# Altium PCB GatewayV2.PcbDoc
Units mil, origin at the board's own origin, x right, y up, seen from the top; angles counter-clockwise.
Board outline 1970 x 2515 mil, 2 copper layers (Top Layer, Bottom Layer); 53 components, 43 nets, 217 pads, 138 vias.
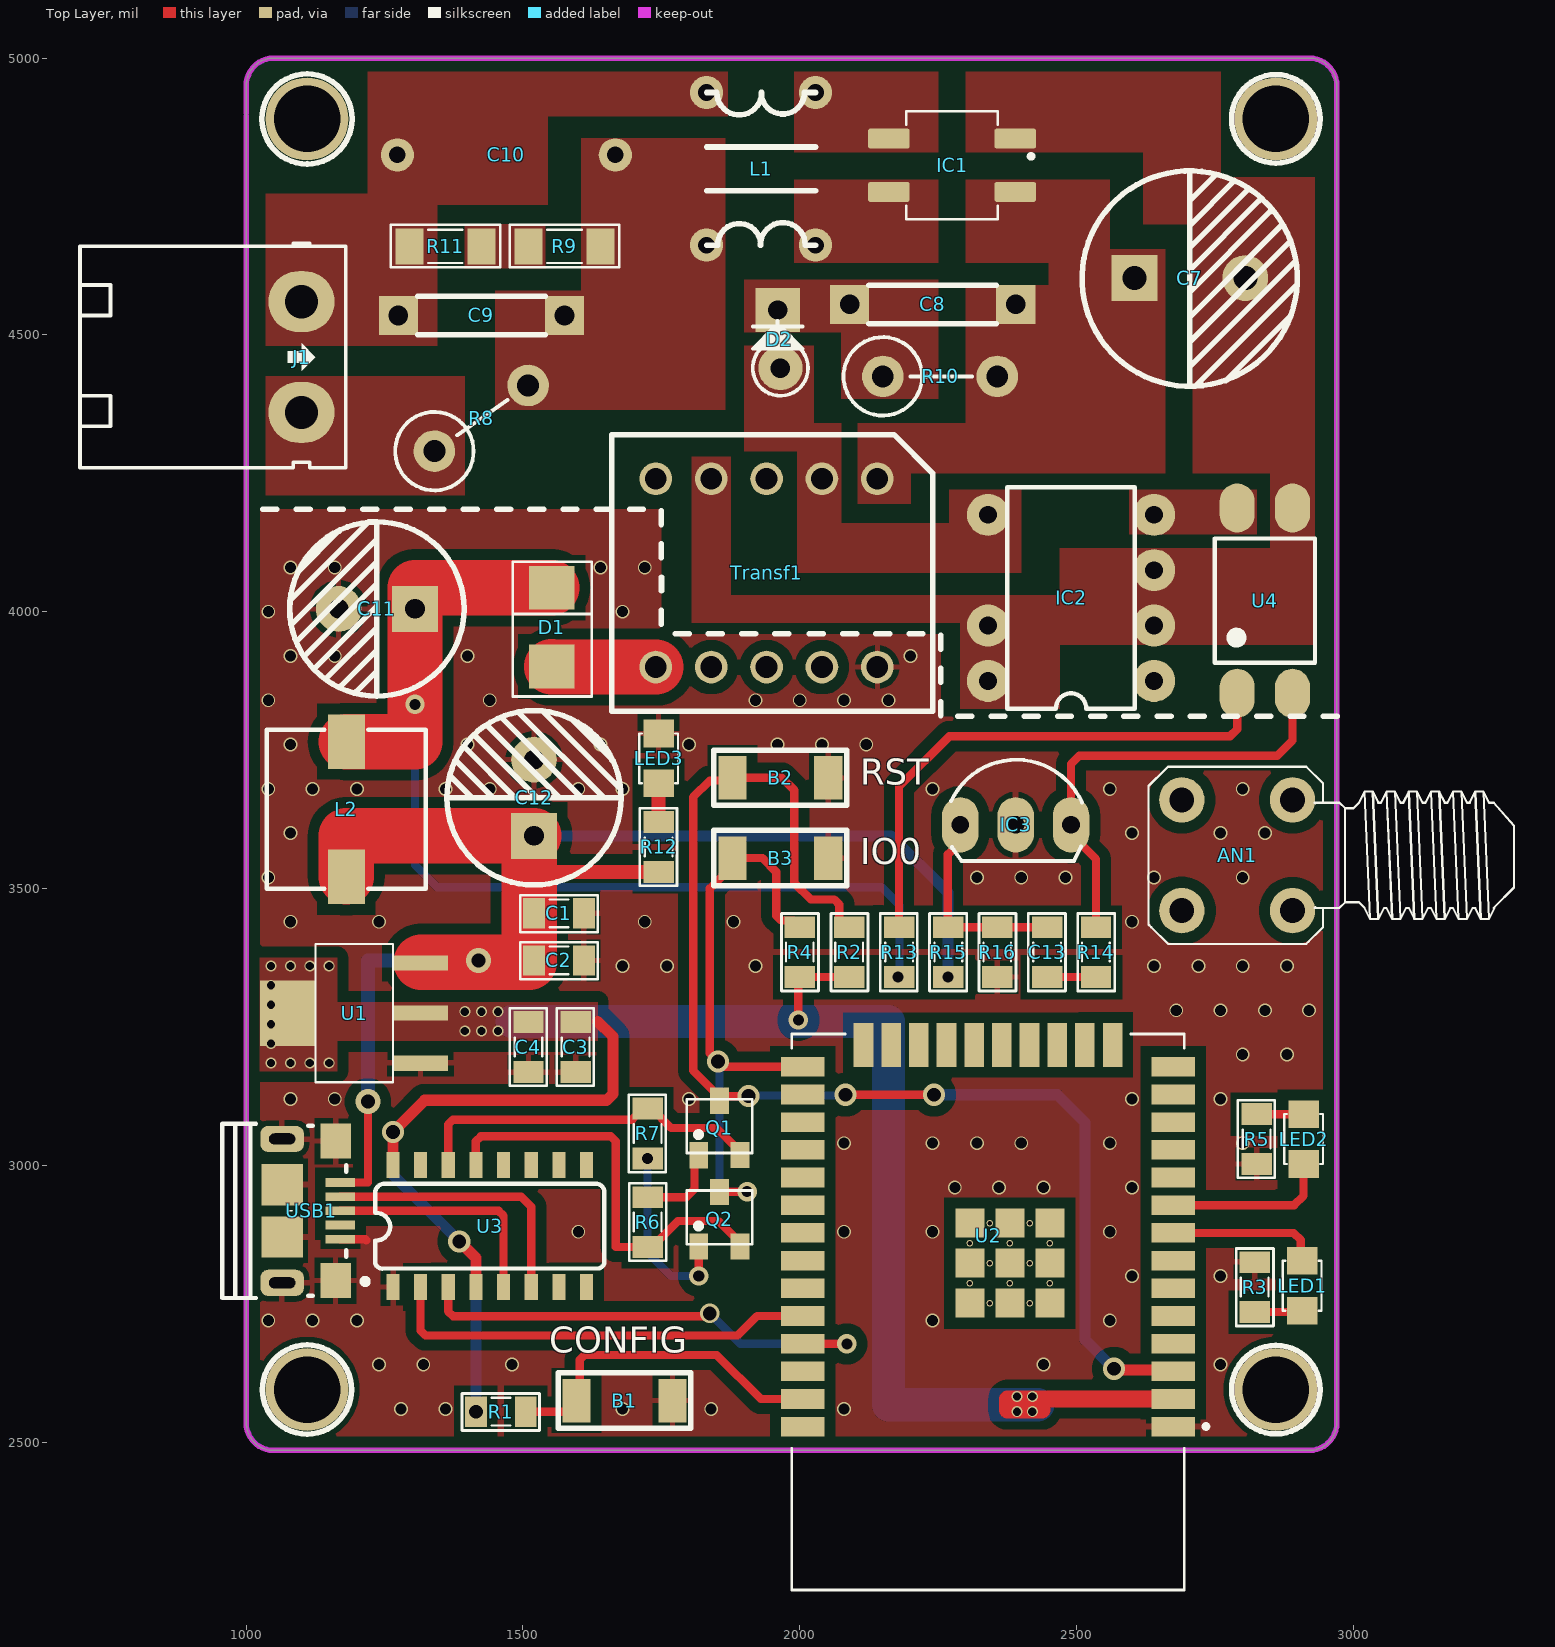
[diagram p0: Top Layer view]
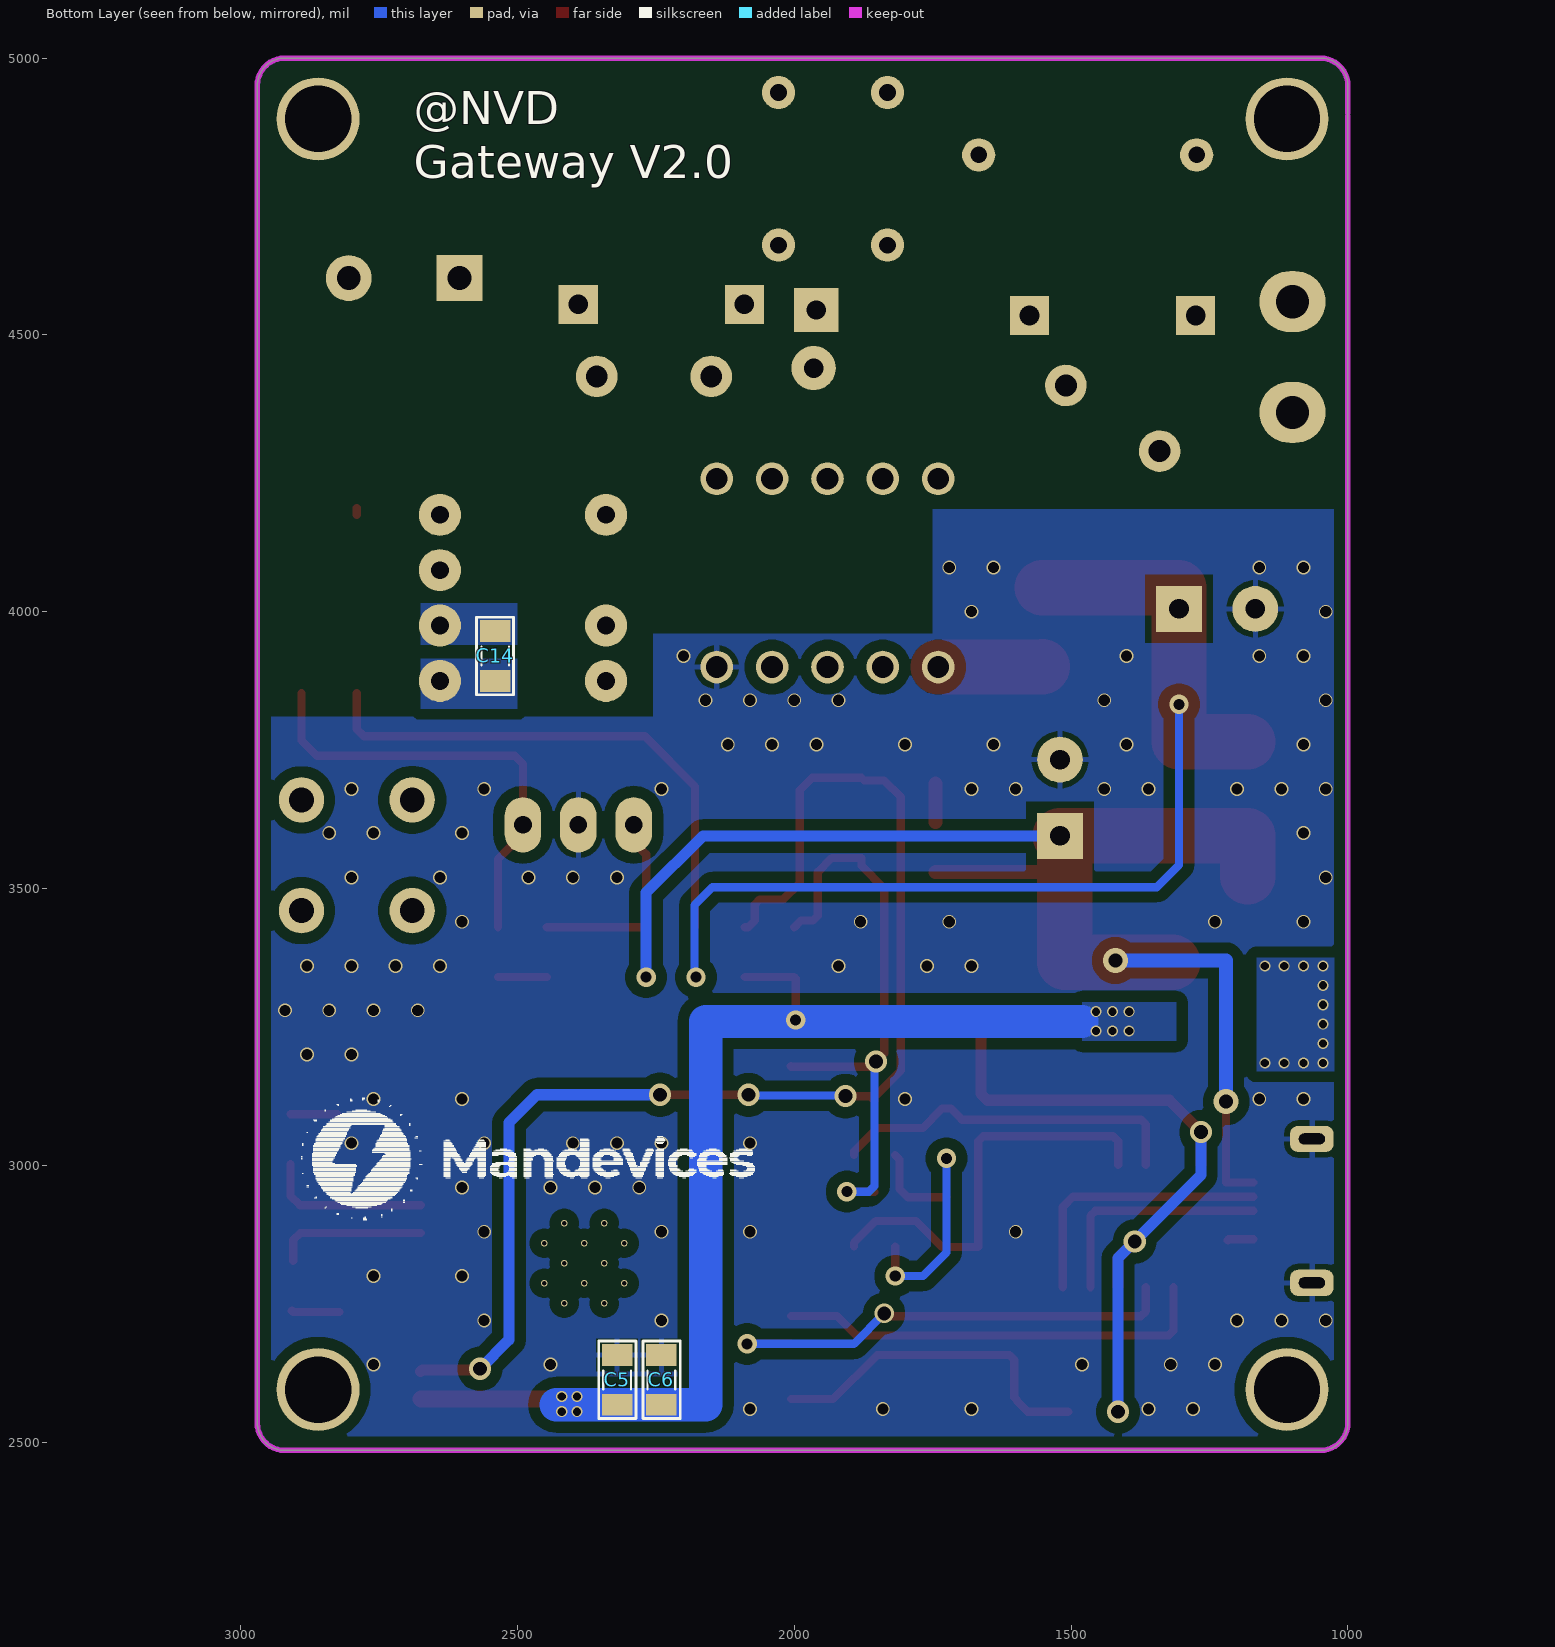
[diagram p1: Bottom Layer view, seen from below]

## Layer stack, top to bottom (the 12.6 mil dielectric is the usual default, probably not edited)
Top Solder: solder mask 0.4, Solder Resist, Dk 3.5
Top Layer: signal copper 1.4
Dielectric 1: dielectric 12.6, FR-4, Dk 4.8
Bottom Layer: signal copper 1.4
Bottom Solder: solder mask 0.4, Solder Resist, Dk 3.5

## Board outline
1050.01,2485 cw(c1050.01,2535) 1000.01,2535 1000.01,2570 1000.47,4895 1000,4900 1000,4950 cw(c1050,4950) 1050,5000 2920,5000 cw(c2920,4950) 2970,4950 2970,2535 cw(c2920,2535) 2920,2485

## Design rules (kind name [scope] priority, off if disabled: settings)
Clearance GND_Clearance [InNet('GND')] p1: gap=15 ignorepadtopadclearanceinfootprint=TRUE
Clearance [All] p2: gap=15 ignorepadtopadclearanceinfootprint=TRUE
PolygonConnect [All] p1: thpad.connectstyle=Relief thpad.reliefconductorwidth=10 thpad.reliefentries=4 thpad.polygonreliefangle="90 Angle" thpad.airgapwidth=10 smdpad.connectstyle=Relief smdpad.reliefconductorwidth=10 smdpad.reliefentries=4 smdpad.polygonreliefangle="90 Angle" smdpad.airgapwidth=10 via.connectstyle=Direct via.reliefconductorwidth=10 via.reliefentries=4 via.polygonreliefangle="90 Angle" via.airgapwidth=10
RoutingVias [All] p1: holewidth=28 width=50 viastyle="Through Hole" minholewidth=10 minwidth=10 maxholewidth=100 maxwidth=100
SolderMaskExpansion [All] p1: expansion=4 istentingtop=FALSE
Width [All] p1: maxlimit=100 minlimit=10 preferedwidth=50
30 further rules are at their usual default settings.

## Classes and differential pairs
component class Power: C7 C8 C9 C10 C11 C12 C13 C14 D1 D2 IC1 IC2 IC3 J1 L1 L2 LED3 R8 R9 R10 R11 R12 R13 R14 R15 R16 Transf1 U4
component class ESP32: AN1 B1 B2 B3 C1 C2 C3 C4 C5 C6 LED1 LED2 Q1 Q2 R1 R2 R3 R4 R5 R6 R7 U1 U2 U3 USB1

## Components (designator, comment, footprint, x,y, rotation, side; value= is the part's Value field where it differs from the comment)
AN1 "ANTENA" "DE ANTEN SMA CONG" 2790,3560 r90 top
B1 "Button 3x4x2.5" "Button 3x4x2.5" 1683.39,2575 r180 top
B2 "Button 3x4x2.5" "Button 3x4x2.5" 1965,3700 r180 top
B3 "Button 3x4x2.5" "Button 3x4x2.5" 1965,3555 r180 top
C1 "10uF" CAP_0805 1562.85,3543.11 r0 top value=33p
C2 "100nF" CAP_0805 1562.85,3458.11 r0 top value=33p
C3 "10uF" CAP_0805 1683.11,3215.86 r270 top value=33p
C4 "100nF" CAP_0805 1598.11,3215.86 r270 top value=33p
C5 "100nF" CAP_0805 2408.11,2610.35 r90 bottom value=33p
C6 "10uF" CAP_0805 2328.11,2610.35 r90 bottom value=33p
C7 "10uF/400V" C10mm 2705,4605 r0 top
C8 "1nF/400V" 103/2KV 2390,4555 r180 top
C9 "14D471K" 103/2KV 1275,4535 r0 top
C10 "0.1uF/275v" "Cap AC filter" 1470,4825 r0 top
C11 "680uF/16V" C8mm 1242.75,4002.3 r180 top
C12 "470uF/16V" C8mm 1517.3,3657.25 r90 top
C13 "100nF" CAP_0805 2534.94,3387.15 r270 top value=33p
C14 "100nF" CAP_0805 2451.89,3922.15 r270 bottom value=33p
D1 "SS14" DO-214AC(SMA) 1555,3950 r270 top value=1N5007
D2 "1N4937" DIO-1AN 1960,4495 r270 top value=1N5007
IC1 "MB6S" MB6S 2280,4795 r180 top
IC2 "TNY264" TNY264 2686.85,3808.46 r90 top
IC3 "TL431" qto-92 2390,3615 r0 top
J1 "KF2" KF2-5.08T 1100,4560 r270 top
L1 "Inductor EE8.3" "Inductor EE8.3" 1930,4800 r90 top
L2 "22uH" L_SMD 1175,3655 r0 top value="150 mH"
LED1 "LED" LED-0805-Red 2907.5,2827.5 r270 top value="LED 3 ly Single Colour"
LED2 "LED" LED-0805-Red 2910,3002.5 r90 top value="LED 3 ly Single Colour"
LED3 "LED" LED-0805-Red 1745,3690 r90 top value="LED 3 ly Single Colour"
Q1 "C1815" SOT23D 1855,3067.5 r0 top
Q2 "C1815" SOT23D 1855,2902.5 r0 top
R1 "10k" RES-SMD-0805 1460,2555 r0 top
R2 "10k" RES-SMD-0805 2089.17,3385 r90 top
R3 "1k" RES-SMD-0805 2821.5,2780 r90 top
R4 "10k" RES-SMD-0805 2000,3385 r90 top
R5 "1k" RES-SMD-0805 2825,3047.5 r270 top
R6 "10k" RES-SMD-0805 1725,2897.5 r90 top
R7 "10k" RES-SMD-0805 1725,3057.5 r270 top
R8 "2R/2W" RES-1WW 1393.24,4327.28 r35 top
R9 "1M" RES-SMD-1206 1575,4660 r0 top
R10 "200k/2W" RES-1WW 2215,4425 r0 top
R11 "1M" RES-SMD-1206 1360,4660 r0 top
R12 "1k" RES-SMD-0805 1745,3575 r270 top
R13 "200R" RES-SMD-0805 2179.33,3385 r270 top
R14 "3.3k" RES-SMD-0805 2535,3385 r90 top
R15 "11k" RES-SMD-0805 2268.5,3385 r270 top
R16 "10k" RES-SMD-0805 2356.67,3385 r90 top
Transf1 "Transformer EE12.7" "Transformer EE12.7" 1940,4070 r180 top
U1 "LM1117-ADJ" LM1117-SOP 1265,3275 r90 top
U2 "ESP32-WROOM-32" MODULE_ESP32-WROOM-32 2340,2735 r180 top
U3 "CH340C" SO016 1440,2890.24 r0 top
U4 "OPTO PC817 SMD" SOP4 2840,4020 r90 top value=PC817
USB1 "USB Micro 5p DIP" "USB Micro 5p DIP" 1065,2917.76 r270 top

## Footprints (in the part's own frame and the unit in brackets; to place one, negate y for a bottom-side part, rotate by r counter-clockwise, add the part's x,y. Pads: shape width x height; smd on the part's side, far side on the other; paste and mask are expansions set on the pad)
103/2KV [mm]
  rect 1.8x1.8 hole 0.9: 1(0,0) 2(7.62,0)
  silkscreen extent 0.89,-0.89 6.73,0.89, body extent -0.19,-1.2 7.81,1.19, height 9.03
"Button 3x4x2.5" [mm]
  rect 1.3x2 smd: 1(-2.2,0) 2(2.2,0)
  silkscreen extent -3.05,-1.27 3.05,1.27, body extent -2.45,-1.45 2.45,1.45, height 2
C8mm [mm]
  rect 2.1x2.1 hole 0.9: 1(-1.581,-0.069)
  round 2.1 hole 0.9: 2(1.919,-0.069)
  silkscreen extent -3.83,-4.07 4.17,3.93, body extent -3.93,-4.14 4.27,4.06, height 13.81
C10mm [mm]
  rect 2.1x2.1 hole 1.1: 1(-2.549,-0.062)
  round 2.1 hole 1.1: 2(2.531,-0.062)
  silkscreen extent -4.96,-5.02 4.92,4.85, body extent -5.01,-5.06 4.96,4.94, height 20.01
"Cap AC filter" [mil]
  round 60 hole 30: 1(-196.85,0) 2(196.85,0)
  body extent -256,-98 256,98, height 472
CAP_0805 [mil]
  rect 39.37x55 smd: 1(-42.85,-88.11) 2(47.15,-88.11)
  silkscreen extent -68,-122 72,-55, body extent -38,-114 42,-64, height 24
"DE ANTEN SMA CONG" [mil]
  round 0 all layers, no hole: 1(0,0)
  round 82 hole 45: 2(-100,-100) 3(100,-100) 4(100,100) 5(-100,100)
  silkscreen extent -160,-500 160,160, body extent -136,-457 139,137, height 394
DIO-1AN [mil] "Diode 1A, W 100mil, L 150mil"
  round 80 hole 35: 1(55,5)
  rect 80x80 hole 35: 2(-50,0)
  silkscreen extent -30,-45 105,55, body extent -64,-50 104,55, height 252
DO-214AC(SMA) [mm] "DO-214AC Diode Smallest Size"
  rect 2x2.1 smd: 1(1.245,-0.076) 2(-2.367,-0.076)
  silkscreen extent -3.56,-1.86 2.62,1.76, body extent -3.13,-1.38 2.07,1.22, height 2.4
"Inductor EE8.3" [mil]
  round 60 hole 30: 1(-137.8,-98.43) 2(-137.8,98.43) 3(137.8,-98.43) 4(137.8,98.43)
  silkscreen extent -138,-98 138,98
KF2-5.08T [mil] "Header 2, 2 pin, hight 300mil, Pin to Pin 200, Colour Green"
  oval 110x120 hole 60: 1(0,0) 2(200,0)
  silkscreen extent -105,-400 300,80, body extent -97,-399 297,73, height 334
L_SMD [mm]
  rect 1.7x2.5 smd: 1(0.15,2.8) 2(0.15,-3.4)
  silkscreen extent -3.5,-3.95 3.8,3.35, body extent -3.5,-3.95 3.8,3.35, height 4.05
LED-0805-Red [mil]
  rect 50x55 smd: 1(0,0) 2(90,0)
  silkscreen extent 0,-35 90,35, body extent 5,-25 85,25, height 43
LM1117-SOP [mm]
  rect 0.7x2.54 smd: 1(-2.3,-1.27) 2(0,-1.27) 3(2.3,-1.27)
  rect 3x2.54 smd: 2(0,4.826)
  silkscreen extent -3.18,0 3.17,3.56, body extent -3.25,-1.78 3.25,5.18, height 1.68
MB6S [mm]
  rrect23% 1.91x0.91 smd: 1(-2.774,0.935) 2(-2.774,-1.515) 3(3.026,-1.515) 4(3.026,0.935)
  silkscreen extent -3.6,-2.77 2.23,2.19, body extent -3.15,-2.61 3.55,2.11, height 2.7
MODULE_ESP32-WROOM-32 [mm]
  rect 2x0.9 smd: 1(-8.5,5.26) 2(-8.5,3.99) 3(-8.5,2.72) 4(-8.5,1.45) 5(-8.5,0.18) 6(-8.5,-1.09) 7(-8.5,-2.36) 8(-8.5,-3.63) 9(-8.5,-4.9) 10(-8.5,-6.17) 11(-8.5,-7.44) 12(-8.5,-8.71) 13(-8.5,-9.98) 14(-8.5,-11.25) 25(8.5,-11.25) 26(8.5,-9.98) 27(8.5,-8.71) 28(8.5,-7.44) 29(8.5,-6.17) 30(8.5,-4.9) 31(8.5,-3.63) 32(8.5,-2.36) 33(8.5,-1.09) 34(8.5,0.18) 35(8.5,1.45) 36(8.5,2.72) 37(8.5,3.99) 38(8.5,5.26)
  rect 0.9x2 smd: 15(-5.715,-12.25) 16(-4.445,-12.25) 17(-3.175,-12.25) 18(-1.905,-12.25) 19(-0.635,-12.25) 20(0.635,-12.25) 21(1.905,-12.25) 22(3.175,-12.25) 23(4.445,-12.25) 24(5.715,-12.25)
  rect 1.33x1.33 smd: 39_1(-2.835,-0.405) 39_2(-1,-0.405) 39_3(0.835,-0.405) 39_4(-2.835,-2.24) 39_5(-1,-2.24) 39_6(0.835,-2.24) 39_7(-2.835,-4.075) 39_8(-1,-4.075) 39_9(0.835,-4.075)
  round 0.3 hole 0.2: 39_10(-1.917,-0.405) 39_11(-0.082,-0.405) 39_12(-2.835,-1.322) 39_13(-1,-1.322) 39_14(0.835,-1.322) 39_15(-1.917,-2.24) 39_16(-0.082,-2.24) 39_17(-2.835,-3.157) 39_18(-1,-3.157) 39_19(0.835,-3.157) 39_20(-1.917,-4.075) 39_21(-0.082,-4.075)
  silkscreen extent -10.1,-12.75 9,12.75, body extent -9.02,-12.75 8.98,12.75, height 3.2
qto-92 [mil] "TO-92"
  oval 66x100 hole 32: 1(-100,0) 2(0,0) 3(100,0)
  silkscreen extent -117,-65 120,118, body extent -109,-66 109,95, height 245
RES-1WW [mm]
  round 1.905 hole 1: 1(-1.651,0) 2(3.6,0)
  silkscreen extent -3.45,-1.8 2.45,1.8
RES-SMD-0805 [mil]
  rect 39.37x55 smd: 1(-45,0) 2(45,0)
  silkscreen extent -70,-34 70,33, body extent -39,-25 39,25, height 31
RES-SMD-1206 [mil]
  rect 50x65 smd: 1(-65,0) 2(65,0)
  silkscreen extent -99,-38 99,39, body extent -63,-31 63,32, height 40
SO016 [mm]
  rect 0.6x1.2 smd: 1(-4.445,-2.8) 2(-3.175,-2.8) 3(-1.905,-2.8) 4(-0.635,-2.8) 5(0.635,-2.8) 6(1.905,-2.8) 7(3.175,-2.8) 8(4.445,-2.8) 9(4.445,2.8) 10(3.175,2.8) 11(1.905,2.8) 12(0.635,2.8) 13(-0.635,2.8) 14(-1.905,2.8) 15(-3.175,2.8) 16(-4.445,2.8)
  silkscreen extent -5.84,-2.67 5.26,1.95, body extent -4.99,-3.13 4.99,3.1, height 1.58
SOP4 [mm]
  oval 2.25x1.6 smd: 1(-4.25,1.27) 2(-4.25,-1.27) 3(4.25,-1.27) 4(4.25,1.27)
  silkscreen extent -2.85,-2.3 2.85,2.3, body extent -4.67,-2.29 4.93,2.31, height 3.6
SOT23D [mm] "SOT 23C - 1-3-2 - BCE"
  rect 0.85x1.2 smd: 1(-0.95,-1.25) 2(0.94,-1.245) 3(0,1.25)
  silkscreen extent -1.5,-1.14 1.5,1.32, body extent -1.5,-1.17 1.5,1.33, height 1.06
TNY264 [mil] "Opto"
  round 76 hole 32: 1(66.54,46.85) 2(166.54,46.85) 3(266.54,46.85) 4(366.54,46.85) 5(366.54,346.85) 7(166.54,346.85) 8(66.54,346.85)
  silkscreen extent 17,82 417,312
"Transformer EE12.7" [mm]
  round 1.5 hole 1: 1(-5.08,-4.318) 2(-2.54,-4.318) 3(0,-4.318) 4(2.54,-4.318) 5(5.08,-4.318) 6(5.08,4.318) 7(2.54,4.318) 8(0,4.318) 9(-2.54,4.318) 10(-5.08,4.318)
  silkscreen extent -7.62,-6.35 7.11,6.35
"USB Micro 5p DIP" [mm]
  rect 0.4x1.35 smd mask+0.05: 1(-1.3,2.675) 2(-0.65,2.675) 3(0,2.675) 4(0.65,2.675) 5(1.3,2.675)
  rrect60% 1.2x2 hole 0.5 slot 1.2 at 90 deg: 5(-3.3,0) 5(3.3,0)
  rect 1.6x1.4 smd: 5(-3.2,2.45) 5(3.2,2.45)
  rect 1.9x1.9 smd paste-10: 5(-1.2,0) 5(1.2,0)
  silkscreen extent -4,-2.75 4,2.95, body extent -3.93,-2.76 3.93,2.9, height 2.85

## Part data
AN1: library part "ANTEN SMA CONG", "Generic Antenna"
C1 C2 C3 C4 C5 C6 C13 C14: library part CapSMD, "Capacitor"
C7 C11 C12: library part "Cap Pol", "Polarized Capacitor (Axial)"
C8: library part Cap2KV, "CAP CERAMIC"
C9: library part Cap2KV, "Capacitor Ceramic 2KV"
C10: library part "Cap AC filter", "Tụ lọc nguồn AC 0.1uf 275v 10mm"
D1: library part "Diode SMD", "Diode Schottky / 1N5819"
D2: library part "Diode SMD", "Diode Schottky / 1N4937"
IC2: "IC Power"
IC3: "Programmable Shunt Regulator"
J1: Manufacturer="Würth Elektronik eiSos GmbH", partNo=691103110002
L2: library part Inductor, "CD73R 22uH 1.23A 7345"
LED1 LED2 LED3: "LED Single colour Green and Red"
Q1 Q2: library part 2SC1815, "NPN 600mW, ECB"
R1 R2 R3 R4 R5 R6 R7 R8 R9 R10 R11 R12 R13 R14 R15 R16: library part "Resistor - SMD", "Resistor", Manufacturer="Generic Components"
Transf1: library part "Tranformer EE16"
U1: "800mA Low-Dropout Linear Regulator"
U2: "Bluetooth, WiFi Transceiver Module 2.4GHz ~ 2.5GHz Surface Mount", Package="Module Espressif Systems"
U3: "USB to serial chip CH340", Package=Package
U4: "Single Opto"
USB1: "USB Type B"

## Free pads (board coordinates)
  round 150 hole 120: 0(1110,2595) 0(1110,4890) 0(2860,2595) 0(2860,4890)

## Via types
v1: diameter 25, hole 20, Top Layer to Bottom Layer, tented both sides, 97 vias
v2: diameter 20, hole 15, Top Layer to Bottom Layer, tented both sides, 22 vias
v3: diameter 40, hole 25, Top Layer to Bottom Layer, tented both sides, 8 vias
v4: diameter 35, hole 20, Top Layer to Bottom Layer, tented both sides, 8 vias
v5: diameter 45, hole 25, Top Layer to Bottom Layer, tented both sides, 2 vias
v6: diameter 35, hole 25, Top Layer to Bottom Layer, tented both sides, 1 vias

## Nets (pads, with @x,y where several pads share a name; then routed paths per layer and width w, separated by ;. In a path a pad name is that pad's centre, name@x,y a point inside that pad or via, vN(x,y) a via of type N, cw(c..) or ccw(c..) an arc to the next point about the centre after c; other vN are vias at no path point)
+3.3V: C3.1 C4.1 C5.1 C6.1 R1.1 R2.1 R4.1 U1.2 U2.2 U3.4 U3.16 | length 3492.7
  Top Layer w15: v4(1997.5,3262.5) 1997.5,3337.5 R4.1 R2.1
  Top Layer w20: U3.16 v3(1265,3060) 1322.5,3117.5 1650.78,3117.5 1662.5,3129.22 1662.5,3232.5 1635,3260 ; v3(1385,2862.5) 1415,2832.5 U3.4
  Top Layer w30: 2437.5,2567.5 2437.5,2557.5 2375,2557.5 2375,2577.91 U2.2
  Bottom Layer w20: v3(1265,3060) 1265,2982.5 v3(1385,2862.5) 1415,2832.5 v3(1415,2555)
  Bottom Layer w60: 1480,3260 2160,3260 2160,2567.5 C6.1 C5.1 2430,2567.5
  other v2: 2392.5,2555 2420,2555 2392.5,2582.5 2420,2582.5 1045,3185 1080,3185 1115,3185 1150,3185 1045,3220 1395,3242.5 1425,3242.5 1455,3242.5 1045,3255 1395,3277.5 1425,3277.5 1455,3277.5 1045,3290 1045,3325 1045,3360 1080,3360 1115,3360 1150,3360
+5: C1.1 C2.1 C12.1 L2.2 R12.2 R15.2 U1.3 USB1.1 | length 2663.2
  Top Layer w15: USB1.1 1220,2968.94 v5(1220,3115)
  Top Layer w25: 1511.29,3535 1511.29,3530 R12.2
  Top Layer w100: L2.2 1180.91,3595 C12.1@1511.29,3595 ; U1.3@1316.19,3366.74 1420,3366.74 1511.29,3366.74 1511.29,3455 1511.29,3530 ; 1511.29,3535 C12.1@1511.29,3595 ; C12.1 C12.1@1511.29,3595
  Bottom Layer w20: C12.1 2165,3595 2267.5,3492.5 v4(2267.5,3340)
  Bottom Layer w25: v5(1220,3115) 1220,3370 v5(1420,3370)
CH340_RXD: U2.35 U3.3 | length 872.3
  Top Layer w15: U3.3 1365,2736.29 1373.79,2727.5 1827.09,2727.5 1832.09,2732.5 v6(1837.5,2732.5) ; U2.35 2005.35,2677.5 v4(2085,2677.5)
  Bottom Layer w15: v6(1837.5,2732.5) 1892.5,2677.5 v4(2085,2677.5)
CH340_TXD: U2.34 U3.2 | length 787.4
  Top Layer w15: U3.2 1315,2701.29 1323.79,2692.5 1887.5,2692.5 1922.91,2727.91 U2.34
D_N: U3.6 USB1.2 | length 497.3
  Top Layer w15: USB1.2 1496.65,2943.35 1515,2925 U3.6
D_P: U3.5 USB1.3 | length 427.3
  Top Layer w15: USB1.3 1456.21,2917.76 1465,2908.97 U3.5
DTR: Q2.2 R6.1 U3.13 | length 761.2
  Top Layer w15: U3.13 1415,3043.71 1423.79,3052.5 1658.71,3052.5 1667.5,3043.71 1667.5,2852.5 R6.1 1732.81,2852.5 1779.73,2899.41 1852.98,2899.41 1892,2860.39 Q2.2
EN: B2.2 Q1.3 R2.2 U2.3 | length 2352.1
  Top Layer w15: v3(1907.5,3125) 1863.29,3125 Q1.3 1855,3123.6 1807.5,3171.1 1807.5,3665 1837.5,3695 1873.39,3695 B2.2 1967.5,3700 1990,3677.5 1990,3510 2020,3480 2062.5,3480 2071.29,3471.21 2071.29,3442.18 2083.47,3430 R2.2 ; v3(2082.5,3127.5) v3(2242.5,3127.5)
  Top Layer w20: v3(2567.5,2632.5) 2569.79,2630.21 2672.35,2630.21 U2.3
  Bottom Layer w15: v3(1907.5,3125) 1908.75,3126.25 2081.25,3126.25 v3(2082.5,3127.5)
  Bottom Layer w20: v3(2242.5,3127.5) 2465,3127.5 2515,3077.5 2515,2685 v3(2567.5,2632.5)
GND: B1.1 B2.1 B3.1 C1.2 C2.2 C3.2 C4.2 C5.2 C6.2 C11.2 C12.2 IC3.2 LED3.2 R3.2 R5.2 R16.1 Transf1.10 U1.1 U2.1 U3.1 USB1.5 | length 47.9
  Top Layer w15: USB1.5@1170.32,2866.57 1214.61,2866.57 cw(c1214.61,2864.29) 1216.89,2864.29
  other v1: 1280,2560 1360,2560 1680,2560 1840,2560 2080,2560 1240,2640 1320,2640 1480,2640 2440,2640 2760,2640 1040,2720 1120,2720 1200,2720 2240,2720 2560,2720 2600,2800 2760,2800 1600,2880 2080,2880 2240,2880 2560,2880 2280,2960 2360,2960 2440,2960 2600,2960 2080,3040 2240,3040 2320,3040 2400,3040 2560,3040 2800,3040 1080,3120 1160,3120 1800,3120 2600,3120 2760,3120 2800,3200 2880,3200 2680,3280 2760,3280 2840,3280 2920,3280 1680,3360 1760,3360 1920,3360 2640,3360 2720,3360 2800,3360 2880,3360 1080,3440 1240,3440 1720,3440 1880,3440 2600,3440 1040,3520 2320,3520 2400,3520 2480,3520 2640,3520 2800,3520 1080,3600 2600,3600 2760,3600 2840,3600 1040,3680 1120,3680 1200,3680 1360,3680 1440,3680 1600,3680 1680,3680 2240,3680 2560,3680 2800,3680 1080,3760 1400,3760 1640,3760 1800,3760 1960,3760 2040,3760 2120,3760 1040,3840 1440,3840 1920,3840 2000,3840 2080,3840 2160,3840 1080,3920 1160,3920 1400,3920 2200,3920 1040,4000 1680,4000 1080,4080 1160,4080 1640,4080 1720,4080
GND_AC: C7.2 C14.1 IC1.2 IC2.2 IC2.3 IC2.7 IC2.8 Transf1.4 U4.3
IO0: B3.2 Q2.3 R4.2 U2.25 | length 1099.1
  Top Layer w15: Q2.3 1855.79,2952.5 v4(1905,2952.5) ; R4.2 1987.81,3442.18 1966.29,3442.18 1957.5,3450.97 1957.5,3530 1932.5,3555 B3.2 1878.39,3541.22 1837.5,3500.33 1837.5,3202.5 v3(1852.5,3187.5) 1862.09,3177.91 U2.25 U2.25@2006.4,3178.96
  Bottom Layer w15: v3(1852.5,3187.5) 1855,3185 1855,2962.5 1865,2952.5 v4(1905,2952.5)
IO5: U2.29
IO18: U2.30
IO23: B1.2 R1.2 U2.37 | length 616.7
  Top Layer w15: R1.2 1578.68,2555 1596.77,2573.09 B1.2 1602.5,2580.73 1602.5,2648.71 1611.29,2657.5 1850,2657.5 1929.59,2577.91 U2.37
IO25: U2.10
IO26: U2.11
IO27: U2.12
IO32: LED1.1 U2.8 | length 273.2
  Top Layer w15: U2.8 2892.09,2877.91 2905,2865 LED1.1@2905,2827.5
IO33: LED2.1 U2.9 | length 299.9
  Top Layer w15: U2.9 2892.91,2927.91 2910,2945 LED2.1
IO35: U2.7
NetC7_1: C7.1 C8.1 IC1.1 R10.2 Transf1.1
NetC8_2: C8.2 D2.2 R10.1
NetC9_1: C9.1 C10.1 J1.1 L1.4 R11.1
NetC9_2: C9.2 C10.2 L1.2 R8.2 R9.2
NetC11_1: C11.1 D1.2 L2.1 R13.2 | length 1975.1
  Top Layer w100: L2.1 1305,3765.24 v4(1305,3832.5) C11.1 1305,4043.2 D1.2
  Bottom Layer w15: v4(1305,3832.5) 1305,3542.5 1345,3502.5 2147.5,3502.5 2180,3470 2180,3342.5 v4(2177.5,3340)
NetC13_1: C13.1 IC3.1 R15.1 R16.2 | length 373.1
  Top Layer w15: IC3.1 2290,3584.2 2267.5,3561.7 2267.5,3431 R15.1 C13.1
NetC13_2: C13.2 R14.1 | length 88.2
  Top Layer w15: C13.2 R14.1
NetC14_2: C14.2 IC2.1
NetD1_1: D1.1 Transf1.6 | length 189
  Top Layer w100: D1.1 1552,3900 Transf1.6
NetD2_1: D2.1 IC2.5 Transf1.2
NetIC1_3: IC1.3 L1.3
NetIC1_4: IC1.4 L1.1
NetIC2_4: IC2.4 U4.4 | length 12.3
  Top Layer w15: U4.4@2790,4175 U4.4
NetIC3_3: IC3.3 R14.2 U4.2 | length 819.6
  Top Layer w15: IC3.3 2490,3725 2505,3740 2862.5,3740 2890,3767.5 U4.2 ; IC3.3@2490,3618.2 2490,3598 2535,3553 R14.2
NetJ1_2: J1.2 R8.1
NetLED1_2: LED1.2 R3.1 | length 87
  Top Layer w15: R3.1 2905,2735 LED1.2
NetLED2_2: LED2.2 R5.1 | length 85
  Top Layer w15: R5.1 LED2.2
NetLED3_1: LED3.1 R12.1 | length 70
  Top Layer w25: R12.1 LED3.1
NetQ1_1: Q1.1 R6.2 | length 155.1
  Top Layer w15: R6.2 1795,2942.5 1810,2957.5 1810,3010.69 Q1.1
NetQ2_1: Q2.1 R7.2 | length 333.4
  Top Layer w15: v4(1817.5,2800) v4(1817.5,2800) 1817.55,2853.24 Q2.1
  Bottom Layer w15: v4(1725,3012.5) 1725,2842.5 1767.5,2800 v4(1817.5,2800)
NetR9_1: R9.1 R11.2
NetR13_1: R13.1 U4.1 | length 972.9
  Top Layer w15: R13.1 2179.33,3684.33 2270,3775 2777.5,3775 2790,3787.5 U4.1
RST: Q1.2 R7.1 U3.14 | length 651
  Top Layer w15: U3.14 1365,3073.71 1373.79,3082.5 1697.18,3082.5 1717.19,3102.5 1732.81,3102.5 1767.82,3067.5 1849.89,3067.5 1892,3025.39 Q1.2
pads on no net: AN1.1 AN1.2 AN1.3 AN1.4 AN1.5 Transf1.3 Transf1.5 Transf1.7 Transf1.8 Transf1.9 U2.4 U2.5 U2.6 U2.13 U2.14 U2.15 U2.16 U2.17 U2.18 U2.19 U2.20 U2.21 U2.22 U2.23 U2.24 U2.26 U2.27 U2.28 U2.31 U2.32 U2.33 U2.36 U2.38 U2.39_1 U2.39_2 U2.39_3 U2.39_4 U2.39_5 U2.39_6 U2.39_7 U2.39_8 U2.39_9 U2.39_10 U2.39_11 U2.39_12 U2.39_13 U2.39_14 U2.39_15 U2.39_16 U2.39_17 U2.39_18 U2.39_19 U2.39_20 U2.39_21 U3.7 U3.8 U3.9 U3.10 U3.11 U3.12 U3.15 USB1.4

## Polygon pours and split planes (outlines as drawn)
GND on Top Layer "100" (solid, pour order 36): 1000,4185 1750,4185 1750,3960 2255,3960 2255,3810 2970,3810 2970,2535 cw(c2920,2535) 2920,2485 1050,2485 cw(c1050,2535) 1000,2535
+3.3V on Top Layer "100" (solid, pour order 32): 1025,3375 1025,3170 1165,3170 1165,3375
+3.3V on Top Layer "100" (solid, pour order 31): 1140,3295 1635,3295 1635,3225 1140,3225
GND_AC on Top Layer "100" (solid, pour order 28): 2470,4030 1875,4030 1875,4280 1805,4280 1805,3980 2470,3980
NetC9_1 on Top Layer "100" (solid, pour order 27): 1345,4735 1545,4735 1545,4895 1345,4895
NetIC2_4 on Top Layer "100" (solid, pour order 26): 2595,4140 2825,4140 2825,4220 2595,4220
GND_AC on Top Layer "100" (solid, pour order 25): 2850,4130 2850,4115 2700,4115 2700,3940 2930,3940 2930,4130
GND_AC on Top Layer "100" (solid, pour order 24): 2710,4375 2710,4250 2850,4250 2850,4130 2930,4130 2930,4375
GND_AC on Top Layer "100" (solid, pour order 22): 2290,4025 2290,3825 2470,3825 2470,3940 2700,3940 2700,4115 2470,4115 2470,4025
NetD2_1 on Top Layer "100" (solid, pour order 21): 1900,4480 2025,4480 2025,4340 2075,4340 2075,4160 2270,4160 2270,4220 2400,4220 2400,4070 1995,4070 1995,4290 1900,4290
NetC7_1 on Top Layer "100" (solid, pour order 19): 2660,4375 2660,4250 2200,4250 2200,4195 2105,4195 2105,4340 2300,4340 2300,4375
NetC8_2 on Top Layer "100" (solid, pour order 17): 2135,4600 2250,4600 2250,4385 2075,4385 2075,4518.57
NetC7_1 on Top Layer "100" (solid, pour order 16): 2450,4590 2300,4590 2300,4375 2450,4375
NetC7_1 on Top Layer "100" (solid, pour order 15): 2300,4780 2560,4780 2560,4655 2660,4655 2660,4375 2450,4375 2450,4630 2300,4630
GND_AC on Top Layer "100" (solid, pour order 14): 2620,4830 2620,4700 2710,4700 2710,4830
GND_AC on Top Layer "100" (solid, pour order 11): 2300,4975 2300,4830 2710,4830 2710,4375 2930,4375 2930,4785 2760,4785 2760,4975
NetC8_2 on Top Layer "100" (solid, pour order 9): 1900,4600 2135,4600 2135,4505 1900,4505
NetIC1_4 on Top Layer "100" (solid, pour order 6): 1990,4780 2250,4780 2250,4630 1990,4630
NetIC1_3 on Top Layer "100" (solid, pour order 5): 1990,4975 1990,4830 2250,4830 2250,4975
NetC9_1 on Top Layer "100" (solid, pour order 4): 1220,4945.93 1220,4975 1870,4975 1870,4895 1345,4895
NetC9_2 on Top Layer "100" (solid, pour order 3): 1450,4365 1450,4580 1605,4580 1605,4855 1865,4855 1865,4365
NetR9_1 on Top Layer "100" (solid, pour order 2): 1395,4700 1395,4620 1540,4620 1540,4700
NetJ1_2 on Top Layer "100" (solid, pour order 0): 1035,4425 1035,4210 1395,4210 1395,4425
NetC9_1 on Top Layer "100" (solid, pour order 1): 1035,4480 1345,4480 1345,4950 1220,4950 1220,4755 1035,4755
GND on Bottom Layer "100" (solid, pour order 35): 1000,4185 1750,4185 1750,3960 2255,3960 2255,3810 2970,3810 2970,2535 cw(c2920,2535) 2920,2485 1050,2485 cw(c1050,2535) 1000,2535
+3.3V on Bottom Layer "100" (solid, pour order 33): 1310,3295 1310,3225 1480,3225 1480,3295
+3.3V on Bottom Layer "100" (solid, pour order 30): 1025,3375 1025,3170 1165,3170 1165,3375
GND_AC on Bottom Layer "100" (solid, pour order 29): 2675,3940 2500,3940 2500,4015 2675,4015
NetC14_2 on Bottom Layer "100" (solid, pour order 23): 2500,3915 2675,3915 2675,3825 2500,3825

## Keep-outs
Keep-Out Layer:
  lines w10: 1000,4900 1000,4950 cw(c1050,4950) 1050,5000 1100,5000 2871.65,5000 2920,5000 cw(c2920,4950) 2970,4950 2970,2535 cw(c2920,2535) 2920,2485 1050.01,2485 cw(c1050.01,2535) 1000.01,2535 1000.01,2570 1000.47,4895

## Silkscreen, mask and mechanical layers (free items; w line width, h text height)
Top Overlay:
  circle w10: c2860,2595 r80.04
  circle w10: c1110,2595 r80.51
  circle w10: c2860,4890 r80.04
  circle w10: c1110,4890 r81.39
  lines w10: 1030,4185 1055,4185 ; 1090.36,4184.78 1115.36,4184.78 ; 1150.71,4185 1175.71,4185 ; 1211.07,4185 1236.07,4185 ; 1271.43,4185 1296.43,4185 ; 1331.79,4184.78 1356.79,4184.78 ; 1392.14,4185 1417.14,4185 ; 1452.5,4185 1477.5,4185 ; 1512.5,4185 1537.5,4185 ; 1572.5,4184.78 1597.5,4184.78 ; 1632.5,4185 1657.5,4185 ; 1692.5,4185 1717.5,4185 ; 1750,3977.5 1750,4002.5 ; 1750,4097.5 1750,4122.5 ; 1750,4157.5 1750,4182.5 ; 1750.22,4037.5 1750.22,4062.5 ; 1775,3960 1800,3960 ; 1835,3960 1860,3960 ; 1895,3960.22 1920,3960.22 ; 1955,3960 1980,3960 ; 2017.5,3960 2042.5,3960 ; 2077.5,3960 2102.5,3960 ; 2137.5,3960.22 2162.5,3960.22 ; 2197.5,3960 2222.5,3960 ; 2254.78,3872.5 2254.78,3897.5 ; 2255,3812.5 2255,3837.5 ; 2255,3932.5 2255,3957.5 ; 2285.54,3811.03 2310.54,3811.03 ; 2345.54,3810.81 2370.54,3810.81 ; 2405.54,3811.03 2430.54,3811.03 ; 2465.54,3811.03 2490.54,3811.03 ; 2525.54,3810.81 2550.54,3810.81 ; 2585.54,3811.03 2610.54,3811.03 ; 2645.54,3811.03 2670.54,3811.03 ; 2705.54,3810.81 2730.54,3810.81 ; 2765.54,3811.03 2790.54,3811.03 ; 2825.54,3811.03 2850.54,3811.03 ; 2885.54,3810.81 2910.54,3810.81 ; 2945.54,3811.03 2970.54,3811.03
  text "RST" at 2109.21,3672.29 h80
  text "IO0" at 2109.21,3528.39 h80
  text "CONFIG" at 1547.5,2645.89 h80
Bottom Overlay:
  drawing of 653 lines, arcs and shapes, not listed
  text "@NVD" at 2687.5,4880 h60
  text "Gateway V2.0" at 2687.5,4782.49 h60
